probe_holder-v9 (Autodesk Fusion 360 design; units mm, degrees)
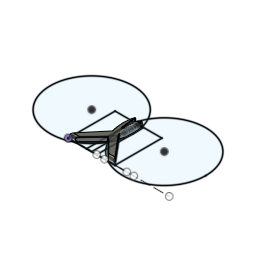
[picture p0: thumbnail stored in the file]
parameter "d24" = 10
sketch "Sketch1" plane through (0, 0, 0) normal (0, 0, 1) x axis (1, 0, 0)
  line L1 (100, 0) -> (0, 0)
  line L2 (100, 100) -> (100, 0)
  line L3 (0, 100) -> (100, 100)
  line L4 (0, 0) -> (0, 100)
  line L5 (50, 0) -> (50, 100)
  line L6 (139.9907, 0) -> (0, 0)
  line L7 (215.4701, 0) -> (100, 0)
  line L8 (125, 0) -> (75, 0)
  line L9 (50, 35) -> (15, 0)
  line L10 (85, 0) -> (15, 0)
  line L11 (50, 35) -> (85, 0)
  line L12 (100, 0) -> (85, 0)
  line L13 (50, 100) -> (42.5, 100)
  line L14 (55, 100) -> (50, 100)
  line L15 (58, 100) -> (50, 100)
  line L16 (42, 100) -> (50, 100)
  line L17 (39.0991, 0) -> (39.0991, 100)
  line L18 (60.9009, 0) -> (60.9009, 100)
  line L19 (50, 59.5877) -> (0, 0)
  line L20 (77.7862, 0) -> (0, 0)
  line L21 (50, 59.5877) -> (100, 0)
  circle C1 centre (50, 100) radius 6
  circle C2 centre (50, 94) radius 5.5
  circle C3 centre (50, 88.5) radius 5
  circle C4 centre (50, 83.5) radius 4.5
  circle C5 centre (50, 79) radius 4
  circle C6 centre (50, 75) radius 3.5
  circle C7 centre (50, 71.5) radius 3
  circle C8 centre (50, 68.5) radius 2.5
  circle C9 centre (-27.5351, 77.5351) radius 88.436
  circle C10 centre (127.5351, 77.5351) radius 88.436
  point P1 (0, 0)
  point P2 (0, 0)
  point P6 (50, 100)
  point P7 (50, 94)
  point P8 (50, 100)
  point P9 (50, 0)
  point P10 (0, 0)
  point P13 (75, 0)
  point P15 (15, 0)
  point P16 (50, 35)
  point P18 (50, 88.5)
  point P19 (50, 83.5)
  point P20 (50, 79)
  point P21 (50, 75)
  point P22 (50, 71.5)
  point P23 (50, 68.5)
  point P24 (42.5, 100)
  point P25 (50, 100)
  point P26 (50, 100)
  point P27 (55, 100)
  point P17 (85, 0)
  point P31 (50, 100)
  point P30 (58, 100)
  point P32 (42, 100)
  point P33 (39.0991, 100)
  point P34 (39.0991, 0)
  point P35 (60.9009, 100)
  point P37 (0, 0)
  point P38 (50, 59.5877)
  point P5 (0, 100)
  point P3 (100, 0)
  horizontal L1
  vertical L2
  horizontal L3
  vertical L4
  coincident P1 P2
  midpoint L3 P6
  coincident C1 P7
  coincident P6 P8
  midpoint L1 P9
  horizontal L6
  coincident P1 P10
  horizontal L7
  horizontal L8
  coincident L6 P13
  horizontal L10
  coincident L1 P15
  coincident L5 P16
  coincident C2 P18
  coincident L5 P18
  coincident C3 P19
  coincident L5 P19
  coincident L5 P20
  coincident C4 P20
  coincident L5 P21
  coincident C5 P21
  coincident C6 P22
  coincident L5 P22
  coincident C7 P23
  coincident L5 P23
  coincident L3 P24
  coincident L3 P25
  perpendicular L5 L13
  coincident P6 P26
  coincident L13 P27
  parallel L13 L14
  coincident P16 C9
  coincident P15 C9
  coincident P17 C10
  coincident P16 C10
  perpendicular L5 L15
  coincident P6 P31
  parallel L3 L16
  coincident C9 P30
  coincident C10 P32
  vertical L17
  coincident L3 P33
  coincident L6 P34
  tangent C10 L17
  coincident L3 P35
  perpendicular L3 L18
  tangent C9 L18
  horizontal L20
  coincident P1 P37
  coincident L5 P38
  dimension "d1" distance P2 P5 = 100
  dimension "d2" distance P2 P3 = 100
  dimension "d3" diameter C1 = 12
  dimension "d4" diameter C2 = 11
  dimension "d11" angle L9 L10 = 45
  dimension "d12" distance P1 P15 = 15
  dimension "d13" distance P3 P17 = 15
  dimension "d14" diameter C3 = 10
  dimension "d15" diameter C4 = 9
  dimension "d16" diameter C5 = 8
  dimension "d17" diameter C6 = 7
  dimension "d18" diameter C7 = 6
  dimension "d19" diameter C8 = 5
  dimension "d109" distance P8 P30 = 8
  dimension "d110" distance P31 P32 = 8
  dimension "d114" angle L19 L20 = 50
extrude "Extrude1" new body sketch "Sketch1" profile of L1 L3 C1 C2 L5 L9 L11 L12 C3 C4 C5 C6 C7 C8 L13 C9 C10 L15 L16 L17 L18 L19 L21 along normal blind 10
fillet "Fillet18" radius 1
fillet "Fillet16" radius 5
fillet "Fillet17" radius 1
